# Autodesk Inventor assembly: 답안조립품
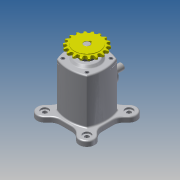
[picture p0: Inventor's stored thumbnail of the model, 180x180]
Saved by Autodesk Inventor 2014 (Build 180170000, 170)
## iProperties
Created: 2016-05
Part Number: 답안조립품
Document SubType Name: Assembly
Designer: 702
Author: 702
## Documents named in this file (11)
- C:\Users\702\Desktop\460507V1004\답안조립품.iam
- C:\Users\702\Desktop\460507V1004\본체.ipt
- C:\Users\702\Desktop\460507V1004\편심축.ipt
- C:\Users\702\Desktop\460507V1004\베어링-6203.ipt
- C:\Users\702\Desktop\460507V1004\키5x5.ipt
- C:\Users\702\Desktop\460507V1004\스프로킷.ipt
- C:\Users\702\Desktop\460507V1004\커버.ipt
- C:\Users\702\Desktop\460507V1004\오일실.ipt
- C:\Users\702\Desktop\460507V1004\M4x0.7x12.ipt
- C:\Users\702\Desktop\460507V1004\부시.ipt
- C:\Users\702\Desktop\460507V1004\슬라이더.ipt
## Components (8 placed, 1 different names)
1. M4x0.7x12:1 — 각도:1
2. M4x0.7x12:3
3. M4x0.7x12:4
4. M4x0.7x12:5
5. M4x0.7x12:2 — 각도:2
6. M4x0.7x12:6
7. M4x0.7x12:7
8. M4x0.7x12:8
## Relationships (2: Angle 2)
- 각도:1 [Angle]: M4x0.7x12:1
- 각도:2 [Angle]: M4x0.7x12:2
